(* Logix 5000 project; controller LogixTester vendor 1 type 14 code 87 rev 20.12; software revision 20.01 *)
// Test PLC for Add-On Instructions

TASK MainTask (continuous, watchdog 500 ms) : MainProgram

MODULES
   Controller : vendor 1 type 14 code 87 (CompactLogixL23E_QB1_Controller 0, rev 20.12)
      LocalENB : vendor 1 type 12 code 190 (CompactLogixL23E_QB1_Ethernet 1, rev 20.11)
         ACS_Drive : vendor 1230 type 43 code 9046 (Ethernet 192.168.0.100, rev 2.22, StandardDataDriven RPI 20 ms)   // EDS Created ACS Drive and Controller
      Local : CompactBus (CompactVirtualAdapter 3, rev 20.11)
         Discrete_Inputs : vendor 1 type 7 code 320 (Compact 1, rev 3.1, Input RPI 20 ms)
         Discrete_Outputs : vendor 1 type 7 code 322 (Compact 2, rev 3.1, Output RPI 20 ms)
END_MODULES

TYPE DriveFaults :
STRUCT
   Positive_Limit : BOOL;   // Positive Limit
   Negative_Limit : BOOL;   // Negative Limit
   E_Stop : BOOL;   // E Stop
   Position_Error : BOOL;   // Position Error
   Feedback_Error : BOOL;   // Feedback Error
   Over_Current : BOOL;   // Overcurrent
   Motor_Over_Temperature : BOOL;   // Motor Over Temperature
   Drive_Over_Temperature : BOOL;   // Drive Over Temperature
   Drive_Over_Voltage : BOOL;   // Drive Over Voltage
   Drive_Under_Voltage : BOOL;   // Drive Under Voltage
   Flash_Error : BOOL;   // Flash Error
   I2T_Limit : BOOL;   // I2T Limit Fault
   Short_Circuit : BOOL;   // Short Circuit Fault
   Watchdog_Reset : BOOL;   // Watchdog Reset
END_STRUCT
END_TYPE

TYPE DriveStatus :
STRUCT
   Drive_Enable : BOOL;   // Drive Enable Input
   Drive_Homed : BOOL;   // Drive Home Input
   Drive_InMotion : BOOL;   // Drive In Motion Input
   Drive_EStop : BOOL;   // Drive E-Stop Input
   rsved_bit00 : BOOL;
   rsved_bit01 : BOOL;
   rsved_bit02 : BOOL;
   rsved_bit03 : BOOL;
   rsved_bit04 : BOOL;
   rsved_bit05 : BOOL;
   rsved_bit06 : BOOL;
   rsved_bit07 : BOOL;
   rsved_bit08 : BOOL;
   Drive_EthAvail : BOOL;   // Drive Ethernet Online
   rsved_bit09 : BOOL;
   rsved_bit10 : BOOL;
   rsved_bit11 : BOOL;
   rsved_bit12 : BOOL;
   rsved_bit13 : BOOL;
   rsved_bit14 : BOOL;
   Drive_BrakeOff : BOOL;   // Brake Output (0 - Enabled; 1- Not Enabled)
   rsved_bit15 : BOOL;
   rsved_bit16 : BOOL;
   rsved_bit17 : BOOL;
   rsrved_bit18 : BOOL;
   rsrved_bit19 : BOOL;
   rsrved_bit20 : BOOL;
   rsrved_bit21 : BOOL;
   rsrved_bit22 : BOOL;
   rsrved_bit23 : BOOL;
   rsrved_bit24 : BOOL;
   Drive_Control : BOOL;
END_STRUCT
END_TYPE

TYPE ToloInput :
STRUCT
   Current_Position : REAL;   // Actuator Current Position
   DriveStatus : DriveStatus;
   DriveFaults : DriveFaults;
   Digital_Input : DINT;   // Digital Input Status
   Digital_Output : DINT;   // Digital Output Status
   Analog_Input : REAL;
   Analog_Output : REAL;
END_STRUCT
END_TYPE

TYPE ToloOutput :
STRUCT
   Control : SINT;
   Move_Select : SINT;
   Target_0_Position : REAL;
   Target_0_Velocity : REAL;
   Target_0_Acceleration : REAL;
   Target_0_Deceleration : REAL;
   Target_0_Force : REAL;
   Motion_Type : SINT;
   Digital_Output : DINT;
END_STRUCT
END_TYPE

ADD_ON_INSTRUCTION ACS_ABSOLUTE_MOVE   (* revision 1.0, vendor Tolomatic, Inc *)
// Move to an Absolute Position
VAR_INPUT
   Position : REAL; {required}   // Absolute Position
   Acceleration : REAL; {required}   // Trajectory Acceleration
   Deceleration : REAL; {required}   // Trajectory Deceleration
   Velocity : REAL; {required}   // Trajectory Constant Velocity
   Force : REAL; {required}   // Force Limit (Percent)
END_VAR
VAR_IN_OUT
   Output : ToloOutput; {required}   // ToloOutput Reference
END_VAR

ROUTINE Logic   (* ladder *)
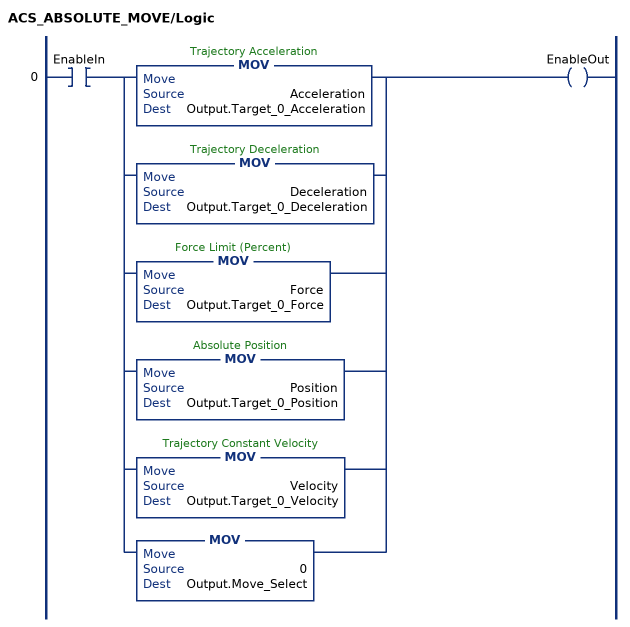
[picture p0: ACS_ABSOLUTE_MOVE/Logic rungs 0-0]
   0: XIC(EnableIn)[MOV(Acceleration,Output.Target_0_Acceleration) ,MOV(Deceleration,Output.Target_0_Deceleration) ,MOV(Force,Output.Target_0_Force) ,MOV(Position,Output.Target_0_Position) ,MOV(Velocity,Output.Target_0_Velocity) ,MOV(0,Output.Move_Select) ]OTE(EnableOut);
END_ROUTINE
END_ADD_ON_INSTRUCTION

ADD_ON_INSTRUCTION ACS_CLEAR_START_MOTION   (* revision 1.0, vendor Tolomatic, Inc *)
// Clears the Start Motion Bit
// Clears Start Motion Timer Enable Line
// Resets Start Motion Timer Accumulator
VAR_IN_OUT
   Output : ToloOutput; {required}   // ToloOutput Reference
   SMTimerEnable : BOOL; {required}   // Start Motion Timer Enable Line
   SMTimer : TIMER; {required}   // Start Motion Timer
END_VAR
VAR
   OutMask : DINT; {access None}   // Mask used to clear start motino bit
END_VAR

ROUTINE Logic   (* ladder *)
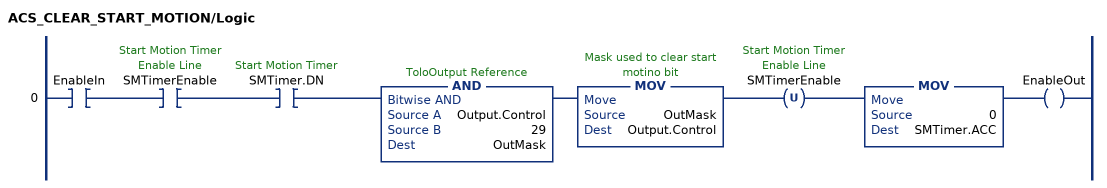
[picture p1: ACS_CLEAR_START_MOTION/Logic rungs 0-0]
   0: XIC(EnableIn)XIC(SMTimerEnable)XIC(SMTimer.DN)AND(Output.Control,29,OutMask)MOV(OutMask,Output.Control)OTU(SMTimerEnable)MOV(0,SMTimer.ACC)OTE(EnableOut);
END_ROUTINE
END_ADD_ON_INSTRUCTION

ADD_ON_INSTRUCTION ACS_DISABLE_DRIVE   (* revision 1.0, vendor Tolomatic, Inc *)
// Disable ACS Drive
VAR_IN_OUT
   Output : ToloOutput; {required}   // ToloOutput Reference
END_VAR

ROUTINE Logic   (* ladder *)
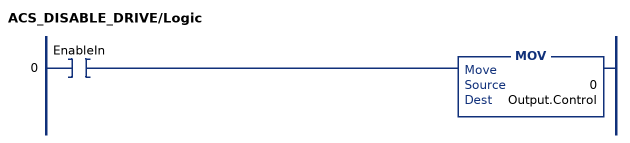
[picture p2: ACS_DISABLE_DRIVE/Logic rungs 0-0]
   0: XIC(EnableIn)MOV(0,Output.Control);
END_ROUTINE
END_ADD_ON_INSTRUCTION

ADD_ON_INSTRUCTION ACS_ENABLE_DRIVE   (* revision 1.0, vendor Tolomatic, Inc *)
// Enable ACS Drive
VAR_IN_OUT
   Output : ToloOutput; {required}   // ToloOutput Reference
END_VAR

ROUTINE Logic   (* ladder *)
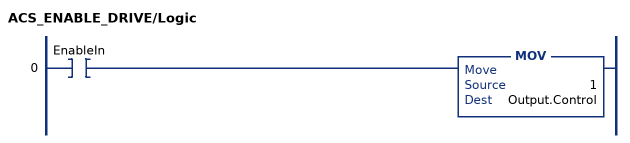
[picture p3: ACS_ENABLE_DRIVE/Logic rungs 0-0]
   0: XIC(EnableIn)MOV(1,Output.Control);
END_ROUTINE
END_ADD_ON_INSTRUCTION

ADD_ON_INSTRUCTION ACS_HOME_MOVE   (* revision 1.0, vendor Tolomatic, Inc *)
// Initiated Homing Routine based on homing profile defined in drive
// Help:
// Add-On Instruction Executes Homing Routine
VAR_IN_OUT
   Output : ToloOutput; {required}   // ACS Control Word
END_VAR

ROUTINE Logic   (* ladder *)
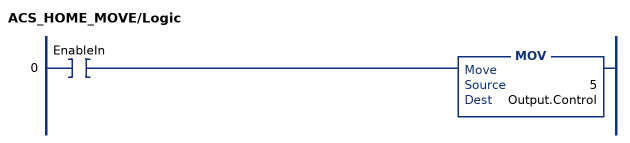
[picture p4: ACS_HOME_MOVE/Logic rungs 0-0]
   0: XIC(EnableIn)MOV(5,Output.Control);
END_ROUTINE
END_ADD_ON_INSTRUCTION

ADD_ON_INSTRUCTION ACS_START_MOTION   (* revision 1.0, vendor Tolomatic, Inc *)
VAR_IN_OUT
   Output : ToloOutput; {required}   // ToloOutput Reference
END_VAR
VAR_INPUT
   PulseWidth : DINT := 200; {visible}   // Time to hold Start Motion bit High in Milliseconds. **This should be greater than the RPI of the drive
END_VAR
VAR_IN_OUT
   StartMotionTimer : TIMER; {required}   // Timer to hold Start Motion Bit High
   SMTimerEnable : BOOL; {required}   // Enable Line for Start Motion Timer
END_VAR

ROUTINE Logic   (* ladder *)
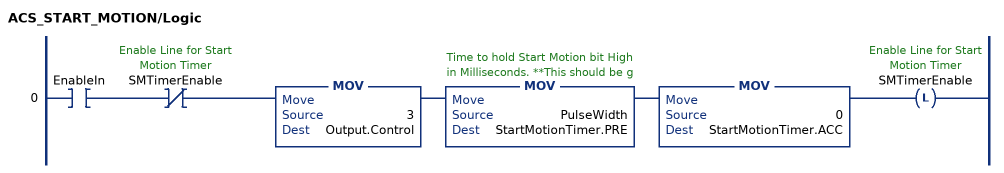
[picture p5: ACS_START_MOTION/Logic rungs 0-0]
   0: XIC(EnableIn)XIO(SMTimerEnable)MOV(3,Output.Control)MOV(PulseWidth,StartMotionTimer.PRE)MOV(0,StartMotionTimer.ACC)OTL(SMTimerEnable);
END_ROUTINE
END_ADD_ON_INSTRUCTION

VAR_GLOBAL   (* controller tags *)
   ToloInputs : ToloInput[1];   // Array of Inputs for ACS Drives
   ToloOutputs : ToloOutput[1];   // Array of Outputs for ACS Drives
END_VAR

PROGRAM MainProgram   (* main routine MainRoutine *)
VAR
   ACS_ABSMOVE_01 : ACS_ABSOLUTE_MOVE;   // Absolute Move 1
   ACS_ABSMOVE_02 : ACS_ABSOLUTE_MOVE;   // Absolute Move 2
   ACS_CmdDisable : BOOL;   // Command to Disable Drive
   ACS_CmdHome : BOOL;   // Send Command to Home
   ACS_Disable : ACS_DISABLE_DRIVE;   // Send Disable Drive Command
   ACS_Disabling : BOOL;   // Disable Command was sent
   ACS_Enable : ACS_ENABLE_DRIVE;   // Send Enable Command
   ACS_Enabled : BOOL;   // Indicates that the drive is ready to roll
   ACS_EnableDelay : TIMER := (PRE := 500);   // Enable Timer Delay
   ACS_Extend : BOOL;   // Extend Actuator
   ACS_Extended : BOOL;   // Actuator is in the extended position
   ACS_Extending : BOOL;   // ACS Extend Command was sent
   ACS_Home : ACS_HOME_MOVE;   // Send Home Command
   ACS_NotEnabled : BOOL;   // Indicates that the Drive is not enabled and the brake is energized
   ACS_Retract : BOOL;   // Retract Actuator
   ACS_Retracted : BOOL;   // ACS is in the Retracted Position
   ACS_Retracting : BOOL;   // Retract Command was sent
   ACS_StartMotion : ACS_START_MOTION := (PulseWidth := 250);   // Send Start Motion Command
   ClearStartMotion : ACS_CLEAR_START_MOTION;   // Clears Start Motion Bit
   StartMotionTimer : TIMER;   // Timer for use in strobing Start Motion bit
   StartMotionTimerEnable : BOOL;   // Enable Start Motion Timer
END_VAR

ROUTINE MainRoutine   (* ladder *)
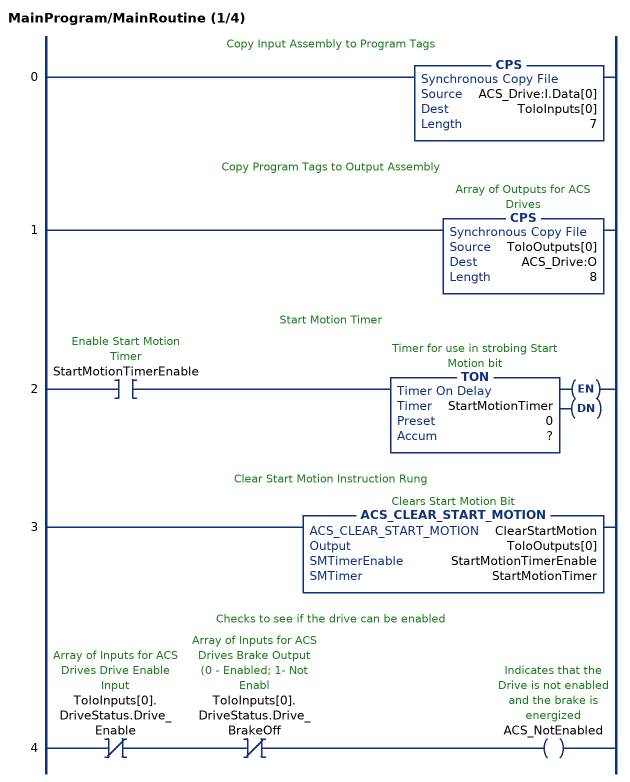
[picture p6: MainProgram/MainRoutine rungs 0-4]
   // Copy Input Assembly to Program Tags
   0: CPS(ACS_Drive:I.Data[0],ToloInputs[0],7);
   // Copy Program Tags to Output Assembly
   1: CPS(ToloOutputs[0],ACS_Drive:O,8);
   // Start Motion Timer
   2: XIC(StartMotionTimerEnable)TON(StartMotionTimer,?,?);
   // Clear Start Motion Instruction Rung
   3: ACS_CLEAR_START_MOTION(ClearStartMotion,ToloOutputs[0],StartMotionTimerEnable,StartMotionTimer);
   // Checks to see if the drive can be enabled
   4: XIO(ToloInputs[0].DriveStatus.Drive_Enable)XIO(ToloInputs[0].DriveStatus.Drive_BrakeOff)OTE(ACS_NotEnabled);
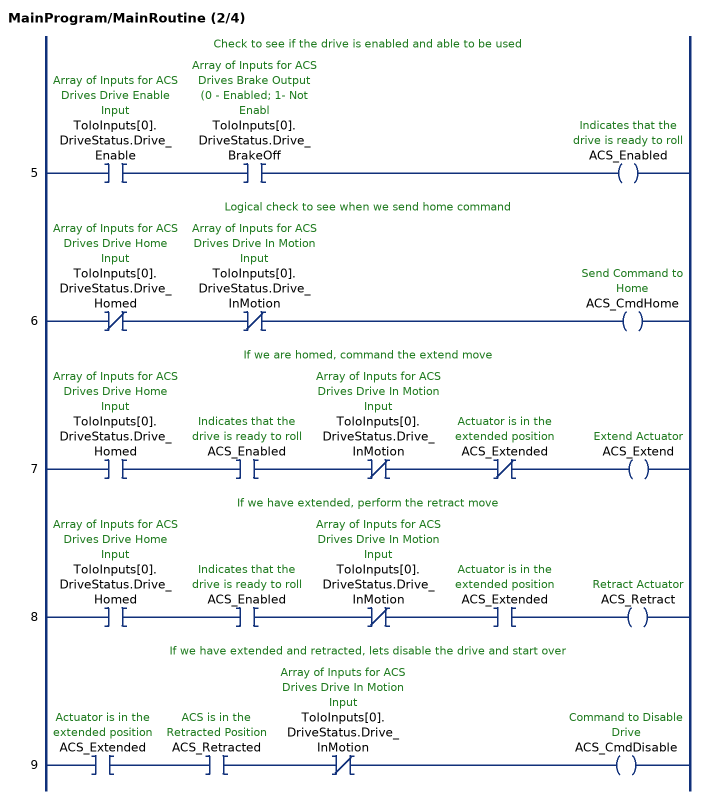
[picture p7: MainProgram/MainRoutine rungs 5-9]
   // Check to see if the drive is enabled and able to be used
   5: XIC(ToloInputs[0].DriveStatus.Drive_Enable)XIC(ToloInputs[0].DriveStatus.Drive_BrakeOff)OTE(ACS_Enabled);
   // Logical check to see when we send home command
   6: XIO(ToloInputs[0].DriveStatus.Drive_Homed)XIO(ToloInputs[0].DriveStatus.Drive_InMotion)OTE(ACS_CmdHome);
   // If we are homed, command the extend move
   7: XIC(ToloInputs[0].DriveStatus.Drive_Homed)XIC(ACS_Enabled)XIO(ToloInputs[0].DriveStatus.Drive_InMotion)XIO(ACS_Extended)OTE(ACS_Extend);
   // If we have extended, perform the retract move
   8: XIC(ToloInputs[0].DriveStatus.Drive_Homed)XIC(ACS_Enabled)XIO(ToloInputs[0].DriveStatus.Drive_InMotion)XIC(ACS_Extended)OTE(ACS_Retract);
   // If we have extended and retracted, lets disable the drive and start over
   9: XIC(ACS_Extended)XIC(ACS_Retracted)XIO(ToloInputs[0].DriveStatus.Drive_InMotion)OTE(ACS_CmdDisable);
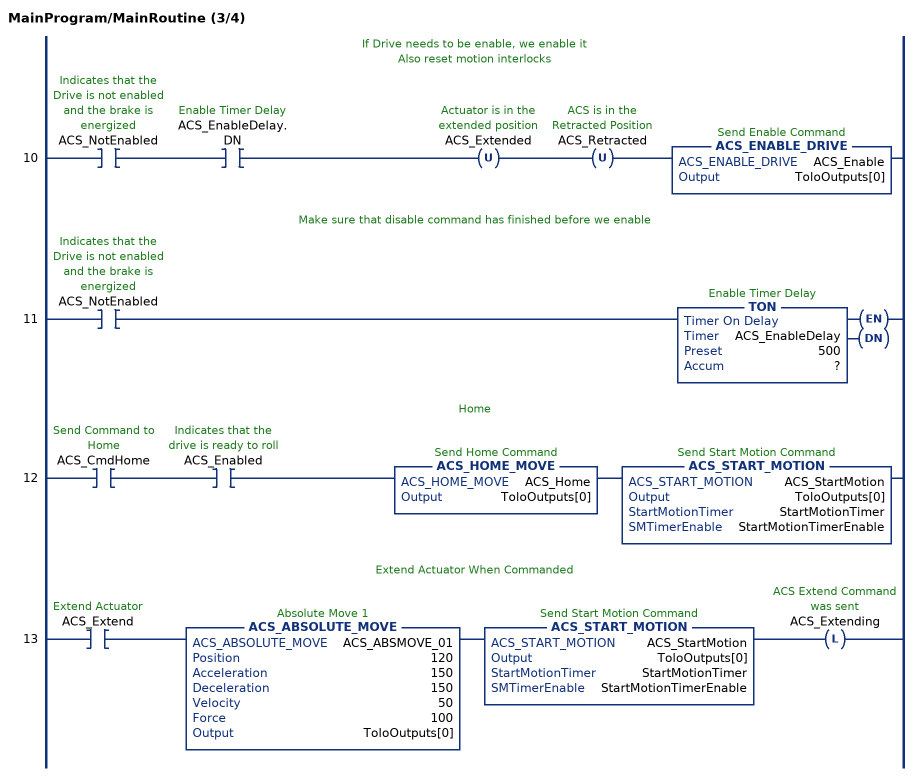
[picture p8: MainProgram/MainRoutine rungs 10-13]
   // If Drive needs to be enable, we enable it
   // Also reset motion interlocks
   10: XIC(ACS_NotEnabled)XIC(ACS_EnableDelay.DN)OTU(ACS_Extended)OTU(ACS_Retracted)ACS_ENABLE_DRIVE(ACS_Enable,ToloOutputs[0]);
   // Make sure that disable command has finished before we enable
   11: XIC(ACS_NotEnabled)TON(ACS_EnableDelay,?,?);
   // Home
   12: XIC(ACS_CmdHome)XIC(ACS_Enabled)ACS_HOME_MOVE(ACS_Home,ToloOutputs[0])ACS_START_MOTION(ACS_StartMotion,ToloOutputs[0],StartMotionTimer,StartMotionTimerEnable);
   // Extend Actuator When Commanded
   13: XIC(ACS_Extend)ACS_ABSOLUTE_MOVE(ACS_ABSMOVE_01,120,150,150,50,100,ToloOutputs[0])ACS_START_MOTION(ACS_StartMotion,ToloOutputs[0],StartMotionTimer,StartMotionTimerEnable)OTL(ACS_Extending);
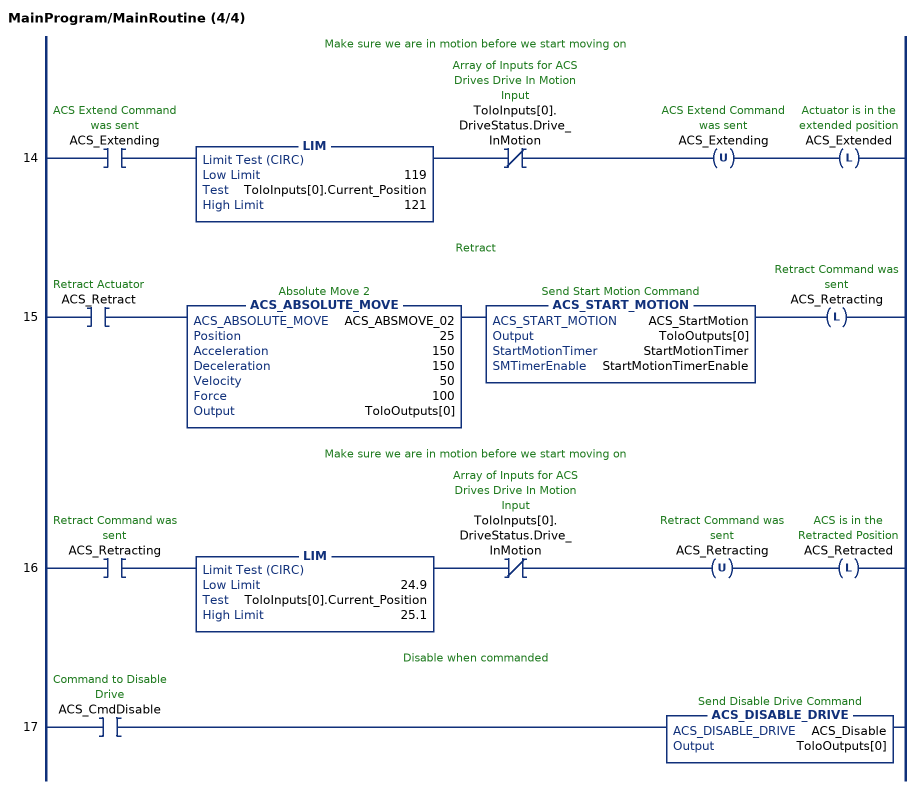
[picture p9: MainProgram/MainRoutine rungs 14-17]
   // Make sure we are in motion before we start moving on
   14: XIC(ACS_Extending)LIM(119,ToloInputs[0].Current_Position,121)XIO(ToloInputs[0].DriveStatus.Drive_InMotion)OTU(ACS_Extending)OTL(ACS_Extended);
   // Retract
   15: XIC(ACS_Retract)ACS_ABSOLUTE_MOVE(ACS_ABSMOVE_02,25,150,150,50,100,ToloOutputs[0])ACS_START_MOTION(ACS_StartMotion,ToloOutputs[0],StartMotionTimer,StartMotionTimerEnable)OTL(ACS_Retracting);
   // Make sure we are in motion before we start moving on
   16: XIC(ACS_Retracting)LIM(24.9,ToloInputs[0].Current_Position,25.1)XIO(ToloInputs[0].DriveStatus.Drive_InMotion)OTU(ACS_Retracting)OTL(ACS_Retracted);
   // Disable when commanded
   17: XIC(ACS_CmdDisable)ACS_DISABLE_DRIVE(ACS_Disable,ToloOutputs[0]);
END_ROUTINE
END_PROGRAM
